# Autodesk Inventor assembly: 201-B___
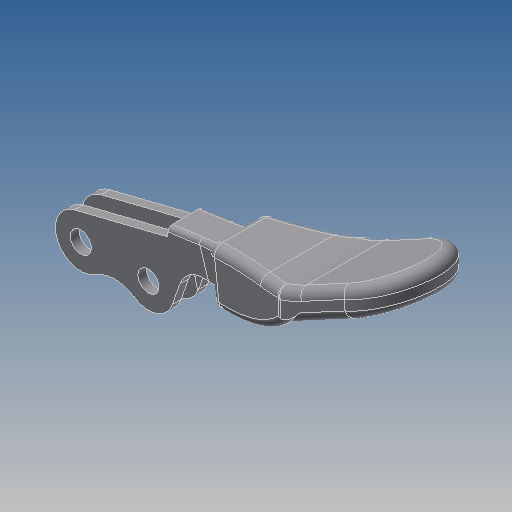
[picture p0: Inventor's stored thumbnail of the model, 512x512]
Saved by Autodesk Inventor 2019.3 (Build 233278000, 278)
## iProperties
Created: 2010-06
Part Number: 201-B___
Material: Ogólny
Document SubType Name: Assembly
Designer: CADENGINEERING4
Author: CADENGINEERING4
Revision Number: ANY
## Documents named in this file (3)
- E:\STRONA\Horizontal toggle clamp\CH-201-BI\201-B___.iam
- E:\STRONA\Horizontal toggle clamp\CH-201-BI\201-B-03___.ipt
- E:\STRONA\Horizontal toggle clamp\CH-201-BI\201-B-05___.ipt
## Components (2 placed, 2 different names)
1. 201-B-03_??_15
2. 201-B-05_??_16
